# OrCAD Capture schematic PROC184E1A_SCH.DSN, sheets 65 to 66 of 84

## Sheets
65 74. POWER SUPPLY #3: size C; title: POWER SUPPLY #3; note: PROC184_SCH
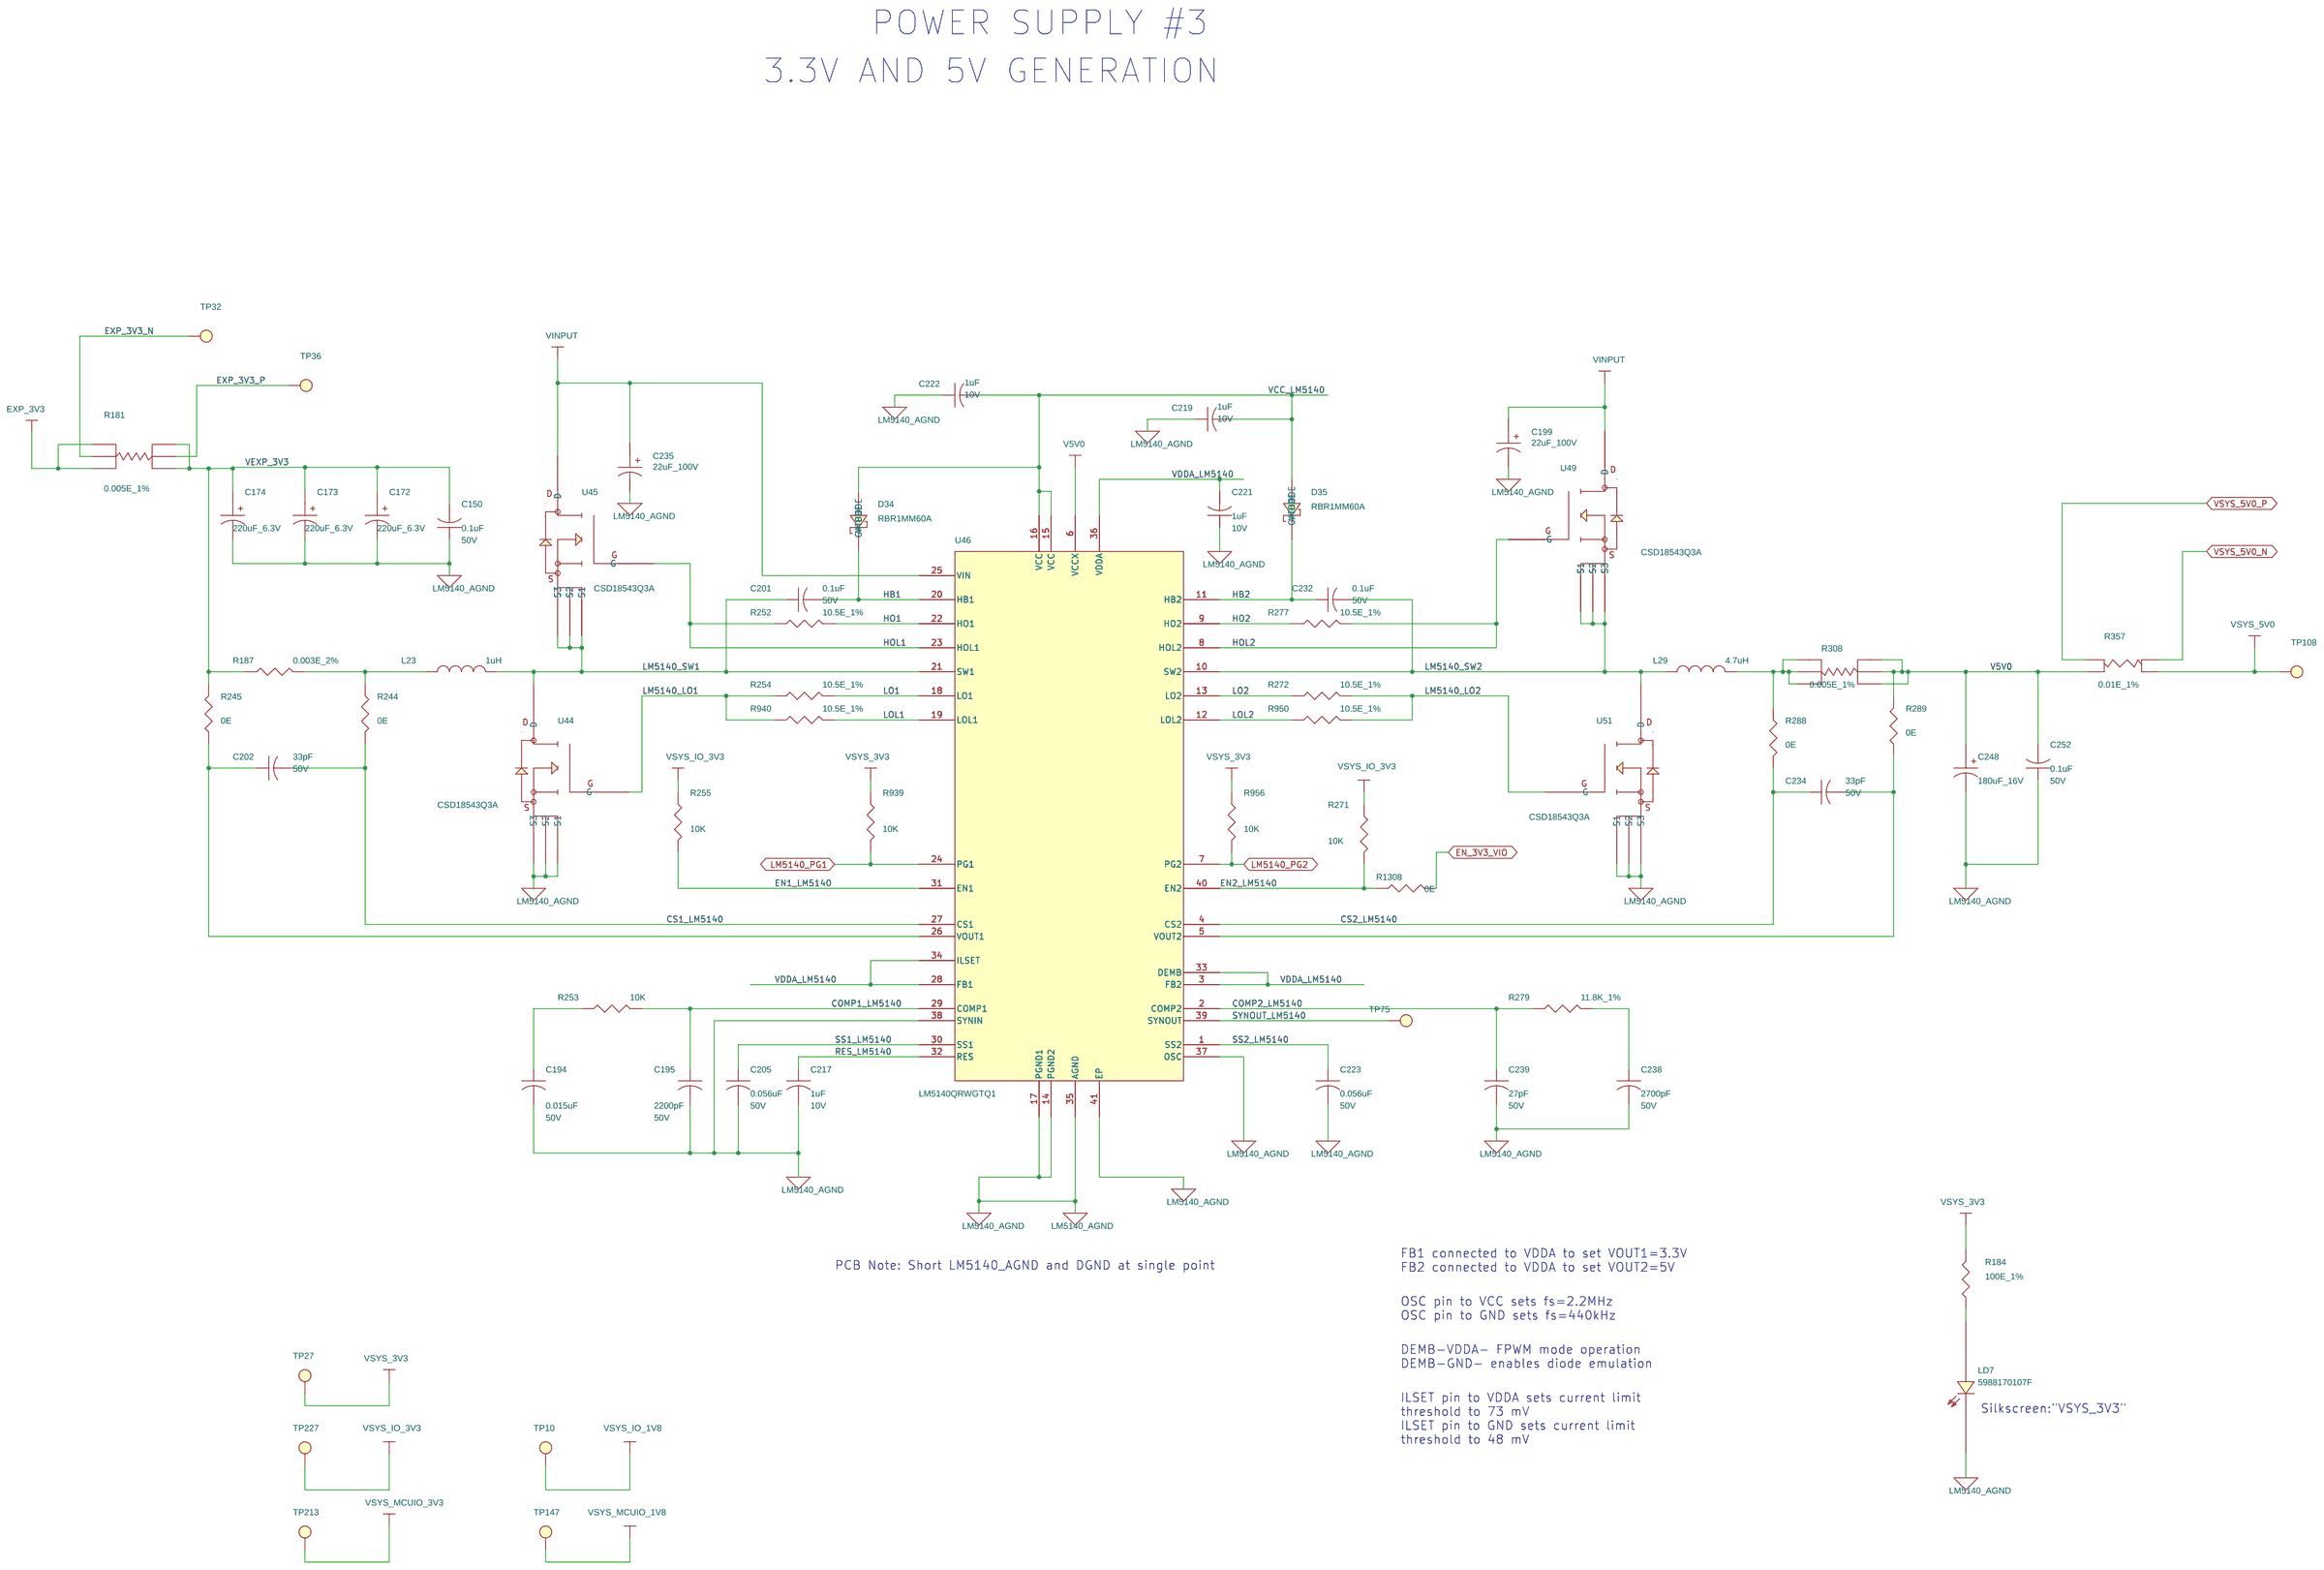
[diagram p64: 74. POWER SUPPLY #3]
66 73. POWER SUPPLY #2: size C; title: POWER SUPPLY #2; note: PROC184_SCH
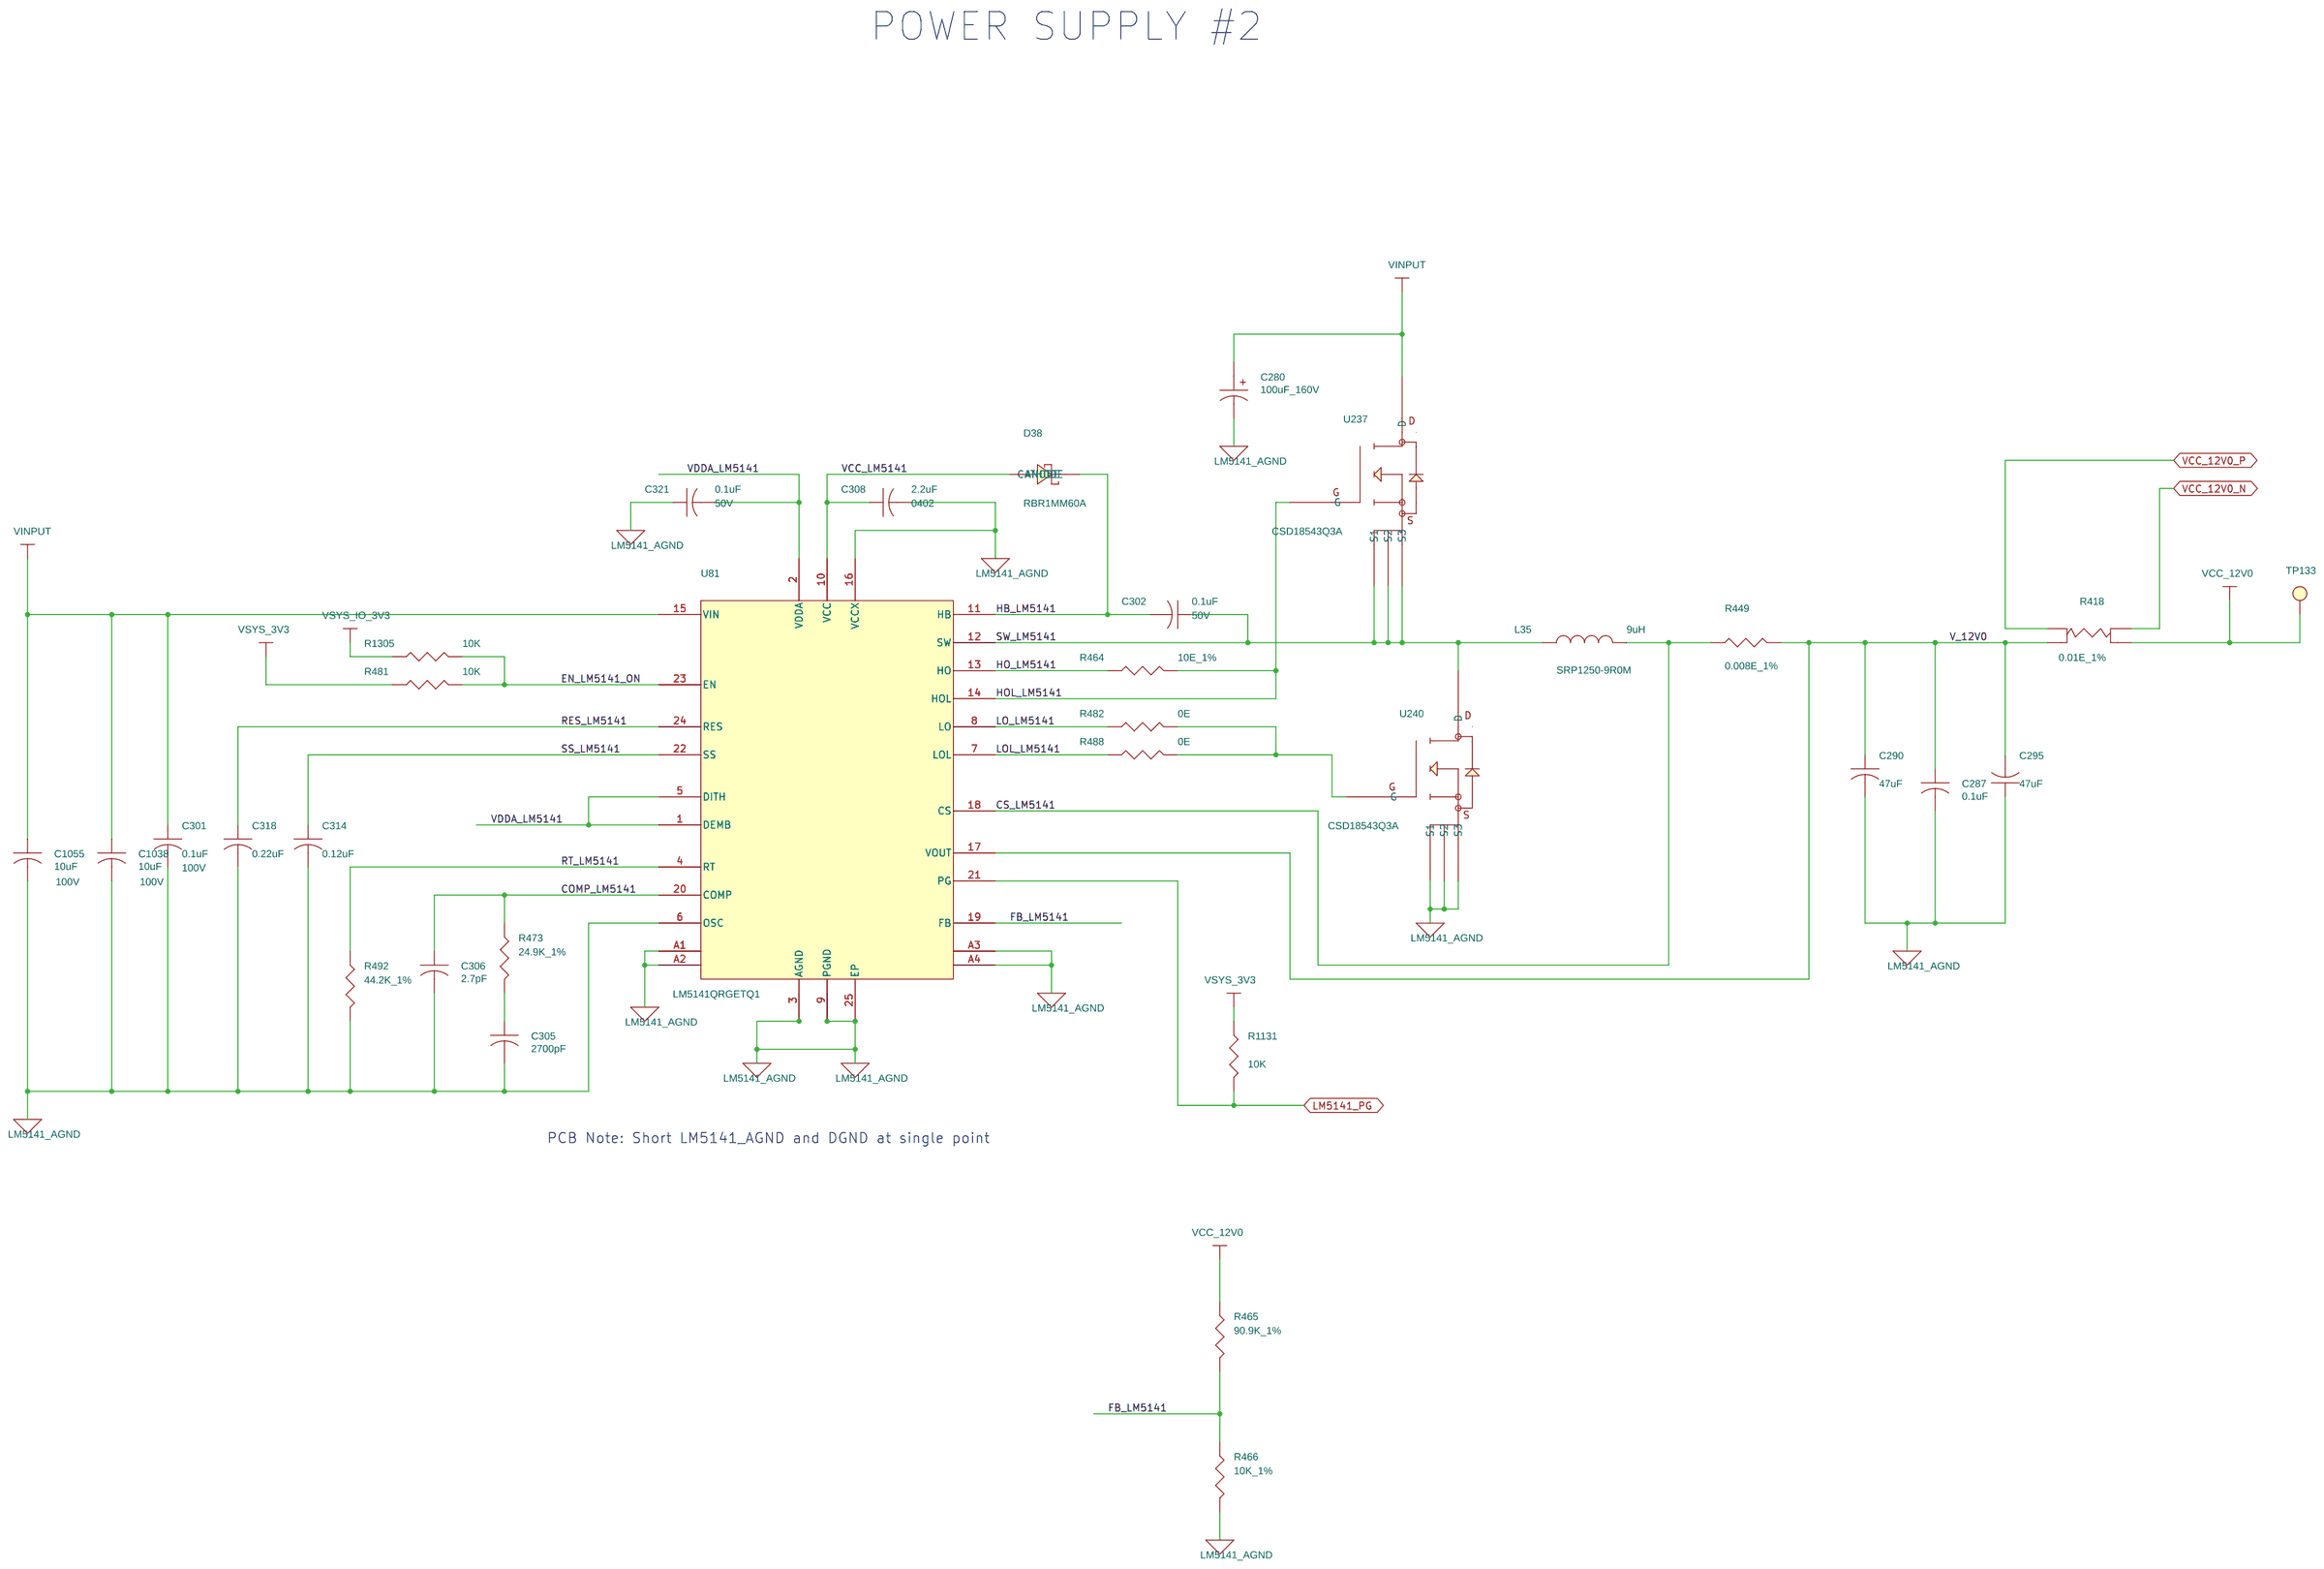
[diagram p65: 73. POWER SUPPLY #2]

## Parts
sheet 73. POWER SUPPLY #2
C280  100uF_160V  [CAPAE_CASE173173_22-5]
C287  0.1uF  [CAP0402_0-75]
C290  47uF  [CAP1206_2]
C295  47uF  [CAP1206_2]
C301  0.1uF  [CAP0603_1]
C302  0.1uF  [CAP0402_0-75]
C305  2700pF  [CAP0402_0-75]
C306  2.7pF  [CAP0402_0-75]
C308  2.2uF  [CAP0402_0-75]
C314  0.12uF  [CAP0603_1]
C318  0.22uF  [CAP0402_0-75]
C321  0.1uF  [CAP0402_0-75]
C1038  10uF  [CAP1210_2-75]
C1055  10uF  [CAP1210_2-75]
D38  RBR1MM60A  [DIO_SOD123F_0-9]
L35  9uH  [IND_SRP1250_550X530_SMD_5-2]
R418  0.01E_1%  [RES_KRL2012_0805-4_0-7_TI]
R449  0.008E_1%  [RES1206_0-75]
R464  10E_1%  [RES0402_0-5]
R465  90.9K_1%  [RES0402_0-5]
R466  10K_1%  [RES0402_0-5]
R473  24.9K_1%  [RES0402_0-5]
R481  10K  [RES0402_0-5]
R482  0E  [RES0402_0-5]
R488  0E  [RES0402_0-5]
R492  44.2K_1%  [RES0402_0-5]
R1131  10K  [RES0402_0-5]
R1305  10K  [RES0402_0-5]
TP133  THRU HOLE  [TP_40X65]
U81  LM5141QRGETQ1  [VQFN24_LM5141_160X160_1]
U237  CSD18543Q3A  [VSONP8_CSD18543Q_120X130_0-9]
U240  CSD18543Q3A  [VSONP8_CSD18543Q_120X130_0-9]
sheet 74. POWER SUPPLY #3
C150  0.1uF  [CAP0402_0-75]
C172  220uF_6.3V  [CAPAE_B6CASE_6]
C173  220uF_6.3V  [CAPAE_B6CASE_6]
C174  220uF_6.3V  [CAPAE_B6CASE_6]
C194  0.015uF  [CAP0805_1]
C195  2200pF  [CAP0805_1-5]
C199  22uF_100V  [CAPAE_CASE8383_10-5]
C201  0.1uF  [CAP0402_0-75]
C202  33pF  [CAP0402_0-75]
C205  0.056uF  [CAP1206_1-25]
C217  1uF  [CAP0402_0-75]
C219  1uF  [CAP0402_0-75]
C221  1uF  [CAP0402_0-75]
C222  1uF  [CAP0402_0-75]
C223  0.056uF  [CAP1206_1-25]
C232  0.1uF  [CAP0402_0-75]
C234  33pF  [CAP0402_0-75]
C235  22uF_100V  [CAPAE_CASE8383_10-5]
C238  2700pF  [CAP0805_1-5]
C239  27pF  [CAP0805_0-75]
C248  180uF_16V  [CAPAE_C6CASE_6]
C252  0.1uF  [CAP0402_0-75]
D34  RBR1MM60A  [DIO_SOD123F_0-9]
D35  RBR1MM60A  [DIO_SOD123F_0-9]
L23  1uH  [IND_HLP5050CE-1R0-01_530X510_SMD_3-5]
L29  4.7uH  [IND_XAL6060_260X270_SMD_6-1]
LD7  5988170107F  [LED_0805_0-7]
R181  0.005E_1%  [RES_KRL3216_1206-6_0-7_TI]
R184  100E_1%  [RES0402_0-5]
R187  0.003E_2%  [RES1206_W_0-75]
R244  0E  [RES0402_0-5]
R245  0E  [RES0402_0-5]
R252  10.5E_1%  [RES0402_0-5]
R253  10K  [RES0402_0-5]
R254  10.5E_1%  [RES0402_0-5]
R255  10K  [RES0402_0-5]
R271  10K  [RES0402_0-5]
R272  10.5E_1%  [RES0402_0-5]
R277  10.5E_1%  [RES0402_0-5]
R279  11.8K_1%  [RES0402_0-5]
R288  0E  [RES0402_0-5]
R289  0E  [RES0402_0-5]
R308  0.005E_1%  [RES_KRL3216_1206-6_0-7_TI]
R357  0.01E_1%  [RES_KRL2012_0805-4_0-7_TI]
R939  10K  [RES0402_0-5]
R940  10.5E_1%  [RES0402_0-5]
R950  10.5E_1%  [RES0402_0-5]
R956  10K  [RES0402_0-5]
R1308  0E  [RES0402_0-5]
TP10  THRU HOLE  [TP_40X65]
TP27  THRU HOLE  [TP_40X65]
TP32  THRU HOLE  [TP_40X65]
TP36  THRU HOLE  [TP_40X65]
TP75  TP40_SMD  [TP40_SMD]
TP108  THRU HOLE  [TP_40X65]
TP147  TP40_SMD  [TP40_SMD]
TP213  THRU HOLE  [TP_40X65]
TP227  THRU HOLE  [TP_40X65]
U44  CSD18543Q3A  [VSONP8_CSD18543Q_120X130_0-9]
U45  CSD18543Q3A  [VSONP8_CSD18543Q_120X130_0-9]
U46  LM5140QRWGTQ1  [QFN40_19-68_240X240_0-9_EP3-4]
U49  CSD18543Q3A  [VSONP8_CSD18543Q_120X130_0-9]
U51  CSD18543Q3A  [VSONP8_CSD18543Q_120X130_0-9]

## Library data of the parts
C280 = CAP_POL: CAP ELECTROLYTIC 100uF 160V 20% CASE_173173; Chkd/date: MANIRAJA/110222; Crtd /date: ALVY/100222; Custom_Duty: 15%; Customs_HS_Code: 85322990; Distributor_name: MOUSER; Distributor_part_number: 647-UUJ2C101MNQ1MS; Footprint Path: Y:\MIS_DATABASE\Library\ALTIUM_TOOL\PCB_FOOTPRINTS\Altium_Footprint_Lib.PcbLib; Height: 22.50MM; Library Path: Y:\MIS_DATABASE\Library\ALTIUM_TOOL\SCHEMATICS_PARTS\MS_DISCRETE_Library.schlib; Manufacturer: NICHICON; Mfr_name: NICHICON; Mfr_part_number: UUJ2C101MNQ1MS; Mistral Part No: 120022020007-R; Package: CASE_173173; Part_type: CAPACITORS\ELECTROLYTIC; Project: TI_J7AHP_EVM_BRD; RoHS: RoHS; Temperature: -40°C+105°C; Tolerance: 20%; Voltage: 160V; Wattage: NA; Weight: 6170mg; Datasheet: Y:\MIS_DATABASE\DATASHEETS\CAPACITORS\UUJ-SER.PDF
C287 = CAP: CAP CERAMIC 0.1uF 50V 10% X7R 0402; Chkd/date: MANIRAJA/261020; Crtd /date: ALVY/211020; Custom_Duty: 15%; Customs_HS_Code: 85322990; Distributor_name: DIGIKEY; Distributor_part_number: 490-10700-1-ND; Footprint Path: Y:\MIS_DATABASE\Library\ALTIUM_TOOL\PCB_FOOTPRINTS\Altium_Footprint_Lib.PcbLib; Height: 0.55MM; Library Path: Y:\MIS_DATABASE\Library\ALTIUM_TOOL\SCHEMATICS_PARTS\MS_DISCRETE_Library.schlib; Mfr_name: MURATA; Mfr_part_number: GRM155R71H104KE14D; Mistral Part No: 120011100014-R; Package: 0402; Part_type: CAPACITORS\CERAMIC; Project: J7_CP; RoHS: RoHS; Temperature: -55°C+125°C; Tolerance: 10%; Voltage: 50V; Wattage: NA; Weight: 3.1mg; Datasheet: Y:\MIS_DATABASE\DATASHEETS\CAPACITORS\GRM155R71H104KE14.PDF
C290 C295 = CAP: CAP CERAMIC 47uF 25V 20% X5R 1206; Chkd/date: VASANTHA/261214; Crtd /date: USMAN/160513; Custom_Duty: 15%; Customs_HS_Code: 85322990; Distributor_name: DIGIKEY; Distributor_part_number: 445-8047-1-ND; Footprint Path: Y:\MIS_DATABASE\Library\ALTIUM_TOOL\PCB_FOOTPRINTS\Altium_Footprint_Lib.PcbLib; Height: 1.80MM; Library Path: Y:\MIS_DATABASE\Library\ALTIUM_TOOL\SCHEMATICS_PARTS\MS_DISCRETE_Library.schlib; Manufacturer: TDK CORPORATION; Mfr_name: TDK CORPORATION; Mfr_part_number: C3216X5R1E476M160AC; Mistral Part No: 120013050002-R; Package: 1206; Part_type: CAPACITORS\CERAMIC; Project: ERP; RoHS: RoHS; Temperature: -55°C+85°C; Tolerance: 20%; Voltage: 25V; Wattage: NA; Weight: 16.2mg; Datasheet: Y:\MIS_DATABASE\DATASHEETS\CAPACITORS\TDK_C-SER-JUL17.PDF
C301 = CAP: CAP CERAMIC 0.1uF 100V 10% X7R 0603; Chkd/date: MANIRAJA/170420; Crtd /date: ALVY/170420; Custom_Duty: 15%; Customs_HS_Code: 85322990; Distributor_name: DIGIKEY; Distributor_part_number: 490-3285-1-ND; Footprint Path: Y:\MIS_DATABASE\Library\ALTIUM_TOOL\PCB_FOOTPRINTS\Altium_Footprint_Lib.PcbLib; Height: 0.90MM; Library Path: Y:\MIS_DATABASE\Library\ALTIUM_TOOL\SCHEMATICS_PARTS\MS_DISCRETE_Library.schlib; Manufacturer: MURATA; Mfr_name: MURATA; Mfr_part_number: GRM188R72A104KA35D; Mistral Part No: 120017010012-R; Package: 0603; Part_type: CAPACITORS\CERAMIC; Project: CUSTOM DCA1000; RoHS: RoHS; Temperature: -55°C+125°C; Tolerance: 10%; Voltage: 100V; Wattage: NA; Weight: 6.3mg; Datasheet: Y:\MIS_DATABASE\DATASHEETS\CAPACITORS\GRM188R72A104KA35.PDF
C302 C321 = CAP: CAP CERAMIC 0.1uF 50V 10% X7R 0402; Chkd/date: MANIRAJA/261020; Crtd /date: ALVY/211020; Custom_Duty: 15%; Customs_HS_Code: 85322990; Distributor_name: DIGIKEY; Distributor_part_number: 490-10700-1-ND; Footprint Path: Y:\MIS_DATABASE\Library\ALTIUM_TOOL\PCB_FOOTPRINTS\Altium_Footprint_Lib.PcbLib; Height: 0.55MM; Library Path: Y:\MIS_DATABASE\Library\ALTIUM_TOOL\SCHEMATICS_PARTS\MS_DISCRETE_Library.schlib; Manufacturer: MURATA; Mfr_name: MURATA; Mfr_part_number: GRM155R71H104KE14D; Mistral Part No: 120011100014-R; Package: 0402; Part_type: CAPACITORS\CERAMIC; Project: J7_CP; RoHS: RoHS; Temperature: -55°C+125°C; Tolerance: 10%; Voltage: 50V; Wattage: NA; Weight: 3.1mg; Datasheet: Y:\MIS_DATABASE\DATASHEETS\CAPACITORS\GRM155R71H104KE14.PDF
C305 = CAP: CAP CERAMIC 2700pF 50V 10% X7R 0402; Chkd/date: VASANTHA/201216; Crtd /date: CHAITHANYA/071111; Custom_Duty: 15%; Customs_HS_Code: 85322990; Distributor_name: DIGIKEY; Distributor_part_number: 490-1306-1-ND; Footprint Path: Y:\MIS_DATABASE\Library\ALTIUM_TOOL\PCB_FOOTPRINTS\Altium_Footprint_Lib.PcbLib; Height: 0.55MM; Library Path: Y:\MIS_DATABASE\Library\ALTIUM_TOOL\SCHEMATICS_PARTS\MS_DISCRETE_Library.schlib; Manufacturer: MURATA; Mfr_name: MURATA; Mfr_part_number: GRM155R71H272KA01D; Mistral Part No: 120011110004-R; Package: 0402; Part_type: CAPACITORS\CERAMIC; Project: DLRL_FPGA_DEV_PF; RoHS: RoHS; Temperature: -55°C+125°C; Tolerance: 10%; Voltage: 50V; Wattage: NA; Weight: 6mg; Datasheet: Y:\MIS_DATABASE\DATASHEETS\CAPACITORS\GRM155R71H272KA01.PDF
C306 = CAP: CAP CERAMIC 2.7pF 50V 0.25pF HI-Q C0G(NP0) 0402; Chkd/date: USMAN/200513; Crtd /date: USMAN/190313; Custom_Duty: 15%; Customs_HS_Code: 85322990; Distributor_name: DIGIKEY; Distributor_part_number: 490-3093-1-ND; Footprint Path: Y:\MIS_DATABASE\Library\ALTIUM_TOOL\PCB_FOOTPRINTS\Altium_Footprint_Lib.PcbLib; Height: 0.55MM; Library Path: Y:\MIS_DATABASE\Library\ALTIUM_TOOL\SCHEMATICS_PARTS\MS_DISCRETE_Library.schlib; Manufacturer: MURATA; Mfr_name: MURATA; Mfr_part_number: GJM1555C1H2R7CB01D; Mistral Part No: 120013030006-R; Package: 0402; Part_type: CAPACITORS\CERAMIC; Project: DTRM; RoHS: RoHS; Temperature: -55°C+125°C; Tolerance: 0.25pF%; Voltage: 50V; Wattage: NA; Weight: 6mg; Datasheet: Y:\MIS_DATABASE\DATASHEETS\CAPACITORS\MURATA-GXX-SER_NOV17.PDF
C308 = CAP: CAP CERAMIC 2.2uF 10V 10% X5R 0402; Chkd/date: MANIRAJA/251120; Crtd /date: ALVY/241120; Custom_Duty: 15%; Customs_HS_Code: 85322990; Distributor_name: MOUSER; Distributor_part_number: 81-GRM155R61A225K01D; Footprint Path: Y:\MIS_DATABASE\Library\ALTIUM_TOOL\PCB_FOOTPRINTS\Altium_Footprint_Lib.PcbLib; Height: 0.55MM; Library Path: Y:\MIS_DATABASE\Library\ALTIUM_TOOL\SCHEMATICS_PARTS\MS_DISCRETE_Library.schlib; Manufacturer: MURATA; Mfr_name: MURATA; Mfr_part_number: GRM155R61A225KE01D; Mistral Part No: 120011100038-R; Package: 0402; Part_type: CAPACITORS\CERAMIC; Project: PLCC_DIGITAL BRD PROTO; RoHS: RoHS; Temperature: -55°C+85°C; Tolerance: 10%; Voltage: 10V; Wattage: NA; Weight: 1.6mg; Datasheet: Y:\MIS_DATABASE\DATASHEETS\CAPACITORS\MURATA-GXX-SER_NOV17.PDF
C314 = CAP: CAP CERAMIC 0.12uF 10V 10% X7R 0603; Chkd/date: MANIRAJA/080519; Crtd /date: ALVY/080519; Custom_Duty: 15%; Customs_HS_Code: 85322990; Distributor_name: DIGIKEY; Distributor_part_number: 311-4056-1-ND; Footprint Path: Y:\MIS_DATABASE\Library\ALTIUM_TOOL\PCB_FOOTPRINTS\Altium_Footprint_Lib.PcbLib; Height: 0.90MM; Library Path: Y:\MIS_DATABASE\Library\ALTIUM_TOOL\SCHEMATICS_PARTS\MS_DISCRETE_Library.schlib; Manufacturer: YAGEO AMERICA; Mfr_name: YAGEO AMERICA; Mfr_part_number: CC0603KRX7R6BB124; Mistral Part No: 120019050003-R; Package: 0603; Part_type: CAPACITORS\CERAMIC; Project: BRUKER_SD820_COMMONDO; RoHS: RoHS; Temperature: -55°C+125°C; Tolerance: 10%; Voltage: 10V; Wattage: NA; Weight: 2mg; Datasheet: Y:\MIS_DATABASE\DATASHEETS\CAPACITORS\YACC-X7R.PDF
C318 = CAP: CAP CERAMIC 0.22uF 16V 10% X7R AUTO 0402; Chkd/date: MANIRAJA/031219; Crtd /date: ALVY/021219; Custom_Duty: 15%; Customs_HS_Code: 85322990; Distributor_name: DIGIKEY; Distributor_part_number: 490-10671-1-ND; Footprint Path: Y:\MIS_DATABASE\Library\ALTIUM_TOOL\PCB_FOOTPRINTS\Altium_Footprint_Lib.PcbLib; Height: 0.55MM; Library Path: Y:\MIS_DATABASE\Library\ALTIUM_TOOL\SCHEMATICS_PARTS\MS_DISCRETE_Library.schlib; Manufacturer: MURATA; Mfr_name: MURATA; Mfr_part_number: GCM155R71C224KE02D; Mistral Part No: 120019020006-R; Package: 0402; Part_type: CAPACITORS\CERAMIC; Project: GRACO_PLC_EXPN BOARD; RoHS: RoHS; Temperature: -55°C+125°C; Tolerance: 10%; Voltage: 16V; Wattage: NA; Weight: 12mg; Datasheet: Y:\MIS_DATABASE\DATASHEETS\CAPACITORS\MURATA-GCM-SER.PDF
C1038 C1055 = CAP: CAP CERAMIC 10uF 100V 10% X7S 1210; Chkd/date: MANIRAJA/280819; Crtd /date: MANIRAJA/280819; Custom_Duty: 15%; Customs_HS_Code: 85322990; Distributor_name: DIGIKEY; Distributor_part_number: 490-16266-1-ND; Footprint Path: Y:\MIS_DATABASE\Library\ALTIUM_TOOL\PCB_FOOTPRINTS\Altium_Footprint_Lib.PcbLib; Height: 2.70MM; Library Path: Y:\MIS_DATABASE\Library\ALTIUM_TOOL\SCHEMATICS_PARTS\MS_DISCRETE_Library.schlib; Manufacturer: MURATA; Mfr_name: MURATA; Mfr_part_number: GRM32EC72A106KE05L; Mistral Part No: 120019080009-R; Package: 1210; Part_type: CAPACITORS\CERAMIC; Project: TI_J7ES_GESI_EXP_BOARD; RoHS: RoHS; Temperature: -55°C+125°C; Tolerance: 10%; Voltage: 100V; Wattage: NA; Weight: 110mg; Datasheet: Y:\MIS_DATABASE\DATASHEETS\CAPACITORS\GRM32EC72A106KE05.PDF
D38 = DIODE_SCHOTTKY: DIODE SCHOTTKY RECTIFIER 60V 1A SOD-123FL; Chkd/date: ALVY/240322; Crtd /date: TAMILARASU/220322; Custom_Duty: 15%; Customs_HS_Code: 85412900; Distributor_name: DIGIKEY; Distributor_part_number: RBR1MM60ACT-ND; Footprint Path: Y:\MIS_DATABASE\Library\ALTIUM_TOOL\PCB_FOOTPRINTS\Altium_Footprint_Lib.PcbLib; Height: 0.90MM; Library Path: Y:\MIS_DATABASE\Library\ALTIUM_TOOL\SCHEMATICS_PARTS\MS_DISCRETE_Library.schlib; Manufacturer: TOREX; Mfr_name: ROHM; Mfr_part_number: RBR1MM60ATR; Mistral Part No: 130022030051-R; Package: SOD-123FL; Part_type: DIODE\SCHOTTKY; Project: TI_J7AHP_EVM_BRD; RoHS: RoHS; Temperature: NA; Tolerance: NA; Voltage: 60V; Wattage: NA; Weight: 27.827mg; Datasheet: Y:\MIS_DATABASE\DATASHEETS\DISCRETES\DIODES\RBR1MM60A.PDF
L35 = INDUCTOR: IND POWER 9uH 10A 20% SMD; Chkd/date: ALVY/150222; Crtd /date: TAMILARASU/150222; Custom_Duty: 24%; Customs_HS_Code: 85437099; Distributor_name: DIGIKEY; Distributor_part_number: SRP1250-9R0MCT-ND; Footprint Path: Y:\MIS_DATABASE\Library\ALTIUM_TOOL\PCB_FOOTPRINTS\Altium_Footprint_Lib.PcbLib; Height: 5.20MM; Library Path: Y:\MIS_DATABASE\Library\ALTIUM_TOOL\SCHEMATICS_PARTS\MS_DISCRETE_Library.schlib; Manufacturer: BOURNS; Mfr_name: BOURNS; Mfr_part_number: SRP1250-9R0M; Mistral Part No: 130022020033-R; Package: SMD; Project: TI_J7AHP_EVM_BRD; RoHS: RoHS; Temperature: -55°C+150°C; Tolerance: 20%; Voltage: NA; Wattage: NA; Weight: 5834mg; Datasheet: Y:\MIS_DATABASE\DATASHEETS\DISCRETES\INDUCTORS\SRP1250-SER-JUN19.PDF
R357 R418 = RESISTOR-4TERM: RES 0.01E 1W 1% 0805-W; Chkd/date: MANIRAJA/301118; Crtd /date: MANIRAJA/301118; Custom_Duty: 15%; Customs_HS_Code: 85332119; Distributor_name: MOUSER; Distributor_part_number: 754-KRL2012ECR010FT5; Footprint Path: Y:\MIS_DATABASE\Library\ALTIUM_TOOL\PCB_FOOTPRINTS\Altium_Footprint_Lib.PcbLib; Height: 0.70MM; Library Path: Y:\MIS_DATABASE\Library\ALTIUM_TOOL\SCHEMATICS_PARTS\MS_DISCRETE_Library.schlib; Manufacturer: SUSUMU; Mfr_name: SUSUMU; Mfr_part_number: KRL2012E-C-R010-F-T5_TI4; Mistral Part No: 110018110013-R; Package: 0805-W; Part_type: RESISTORS\FIXED; Project: TI_J7ES_EVM_SOM; RoHS: RoHS; Temperature: -55°C+175°C; Tolerance: 1%; Voltage: NA; Wattage: 1W; Weight: NA; Datasheet: Y:\MIS_DATABASE\DATASHEETS\RESISTORS\KRL_TI-SERIES.PDF
R449 = RESISTOR: RES 0.008E 1W 1% AUTO 1206; Chkd/date: ALVY/040122; Crtd /date: MANIRAJA/040122; Custom_Duty: 15%; Customs_HS_Code: 85332119; Distributor_name: DIGIKEY; Distributor_part_number: RHM.008ALCT-ND; Footprint Path: Y:\MIS_DATABASE\Library\ALTIUM_TOOL\PCB_FOOTPRINTS\Altium_Footprint_Lib.PcbLib; Height: 0.59MM; Library Path: Y:\MIS_DATABASE\Library\ALTIUM_TOOL\SCHEMATICS_PARTS\MS_DISCRETE_Library.schlib; Manufacturer: ROHM; Mfr_name: ROHM; Mfr_part_number: PMR18EZPFU8L00; Mistral Part No: 110022010001-R; Package: 1206; Part_type: RESISTORS\FIXED; Project: BRUKER_SD820_COMMONDO; RoHS: RoHS; Temperature: -55°C+155°C; Tolerance: 1%; Voltage: NA; Wattage: 1W; Weight: 16.2mg; Datasheet: Y:\MIS_DATABASE\DATASHEETS\RESISTORS\PMR-SER_REVJ.PDF
R464 = RESISTOR: RES 10E 1/10W 1% 0402; Chkd/date: VASANTHA/201216; Crtd /date: MAZHAR/120505; Custom_Duty: 15%; Customs_HS_Code: 85332119; Distributor_name: DIGIKEY; Distributor_part_number: P10.0LCT-ND; Footprint Path: Y:\MIS_DATABASE\Library\ALTIUM_TOOL\PCB_FOOTPRINTS\Altium_Footprint_Lib.PcbLib; Height: 0.40MM; Library Path: Y:\MIS_DATABASE\Library\ALTIUM_TOOL\SCHEMATICS_PARTS\MS_DISCRETE_Library.schlib; Manufacturer: PANASONIC-ECG; Mfr_name: PANASONIC-ECG; Mfr_part_number: ERJ-2RKF10R0X; Mistral Part No: 110009030203-R; Package: 0402; Part_type: RESISTORS\FIXED; Project: CTP02_REVA_BASE; RoHS: RoHS; Temperature: -55°C+155°C; Tolerance: 1%; Voltage: NA; Wattage: 1/10W; Weight: 0.8mg; Datasheet: Y:\MIS_DATABASE\DATASHEETS\RESISTORS\PAN-ERJSER_NOV17.PDF
R465 = RESISTOR: RES 90.9K 1/10W 1% 0402; Chkd/date: ALVY/210222; Crtd /date: TAMILARASU/210222; Custom_Duty: 15%; Customs_HS_Code: 85332119; Distributor_name: DIGIKEY; Distributor_part_number: 2019-RK73G1ETTP9092FCT-ND; Footprint Path: Y:\MIS_DATABASE\Library\ALTIUM_TOOL\PCB_FOOTPRINTS\Altium_Footprint_Lib.PcbLib; Height: 0.40MM; Library Path: Y:\MIS_DATABASE\Library\ALTIUM_TOOL\SCHEMATICS_PARTS\MS_DISCRETE_Library.schlib; Manufacturer: KOA SPEER; Mfr_name: KOA SPEER; Mfr_part_number: RK73G1ETTP9092F; Mistral Part No: 110022020011-R; Package: 0402; Part_type: RESISTORS\FIXED; Project: TI_J7AHP_EVM_BRD; RoHS: RoHS; Temperature: -55°C+155°C; Tolerance: 1%; Voltage: NA; Wattage: 1/10W; Weight: 0.65mg; Datasheet: Y:\MIS_DATABASE\DATASHEETS\RESISTORS\RK73G-SER.PDF
R466 = RESISTOR: RES 10K 1/16W 1% 0402; Chkd/date: VASANTHA/201216; Crtd /date: GEETHA/290506; Custom_Duty: 15%; Customs_HS_Code: 85332119; Distributor_name: DIGIKEY; Distributor_part_number: 311-10.0KLRTR-ND; Footprint Path: Y:\MIS_DATABASE\Library\ALTIUM_TOOL\PCB_FOOTPRINTS\Altium_Footprint_Lib.PcbLib; Height: 0.40MM; Library Path: Y:\MIS_DATABASE\Library\ALTIUM_TOOL\SCHEMATICS_PARTS\MS_DISCRETE_Library.schlib; Manufacturer: YAGEO AMERICA; Mfr_name: YAGEO AMERICA; Mfr_part_number: RC0402FR-0710KL; Mistral Part No: 110015090015-R; Package: 0402; Part_type: RESISTORS\FIXED; Project: VOCERA; RoHS: RoHS; Temperature: -55°C+155°C; Tolerance: 1%; Voltage: NA; Wattage: 1/16W; Weight: 0.65mg; Datasheet: Y:\MIS_DATABASE\DATASHEETS\RESISTORS\RCXXXXL-SER_MAR18.PDF
R473 = RESISTOR: RES 24.9K 1/16W 1% 0402; Chkd/date: MANIRAJA/121017; Crtd /date: MANIRAJA/121017; Custom_Duty: 15%; Customs_HS_Code: 85332119; Distributor_name: DIGIKEY; Distributor_part_number: 311-24.9KLRCT-ND; Footprint Path: Y:\MIS_DATABASE\Library\ALTIUM_TOOL\PCB_FOOTPRINTS\Altium_Footprint_Lib.PcbLib; Height: 0.40MM; Library Path: Y:\MIS_DATABASE\Library\ALTIUM_TOOL\SCHEMATICS_PARTS\MS_DISCRETE_Library.schlib; Manufacturer: YAGEO AMERICA; Mfr_name: YAGEO AMERICA; Mfr_part_number: RC0402FR-0724K9L; Mistral Part No: 110009030538-R; Package: 0402; Part_type: RESISTORS\FIXED; Project: P4_RADAR_DI; RoHS: RoHS; Temperature: -55°C+155°C; Tolerance: 1%; Voltage: NA; Wattage: 1/16W; Weight: 0.65mg; Datasheet: Y:\MIS_DATABASE\DATASHEETS\RESISTORS\RCXXXXL-SER_MAR18.PDF
R253 R255 R271 R481 R939 R956 R1131 R1305 = RESISTOR: RES 10K 1/16W 5% 0402; Chkd/date: VASANTHA/061216; Crtd /date: MAZHAR/230805; Custom_Duty: 15%; Customs_HS_Code: 85332119; Distributor_name: DIGIKEY; Distributor_part_number: 311-10KJRCT-ND; Footprint Path: Y:\MIS_DATABASE\Library\ALTIUM_TOOL\PCB_FOOTPRINTS\Altium_Footprint_Lib.PcbLib; Height: 0.40MM; Library Path: Y:\MIS_DATABASE\Library\ALTIUM_TOOL\SCHEMATICS_PARTS\MS_DISCRETE_Library.schlib; Manufacturer: YAGEO AMERICA; Mfr_name: YAGEO AMERICA; Mfr_part_number: RC0402JR-0710KL; Mistral Part No: 110011060021-R; Package: 0402; Part_type: RESISTORS\FIXED; Project: HSE; RoHS: RoHS; Temperature: -55°C+155°C; Tolerance: 5%; Voltage: NA; Wattage: 1/16W; Weight: 0.65mg; Datasheet: Y:\MIS_DATABASE\DATASHEETS\RESISTORS\RCXXXXL-SER_MAR18.PDF
R244 R245 R288 R289 R482 R488 R1308 = RESISTOR: RES 0E 1/10W JUMPER 0402; Chkd/date: VASANTHA/061216; Crtd /date: NAVEED/201014; Custom_Duty: 15%; Customs_HS_Code: 85332119; Distributor_name: DIGIKEY; Distributor_part_number: P0.0JCT-ND; Footprint Path: Y:\MIS_DATABASE\Library\ALTIUM_TOOL\PCB_FOOTPRINTS\Altium_Footprint_Lib.PcbLib; Height: 0.40MM; IBISSP_MODLES: VALUE REPEATING 2 TIME; Library Path: Y:\MIS_DATABASE\Library\ALTIUM_TOOL\SCHEMATICS_PARTS\MS_DISCRETE_Library.schlib; Manufacturer: PANASONIC-ECG; Mfr_name: PANASONIC-ECG; Mfr_part_number: ERJ-2GE0R00X; Mistral Part No: 110018030052-R; Package: 0402; Part_type: RESISTORS\FIXED; Project: AEGIS POM; RoHS: RoHS; Temperature: -55°C+155°C; Tolerance: NA; Voltage: NA; Wattage: 1/10W; Weight: 0.8mg; Datasheet: Y:\MIS_DATABASE\DATASHEETS\RESISTORS\PAN-ERJSER_NOV17.PDF
R492 = RESISTOR: RES 44.2K 1/16W 1% 0402; Chkd/date: ALVY/041120; Crtd /date: ALVY/041120; Custom_Duty: 15%; Customs_HS_Code: 85332119; Distributor_name: DIGIKEY; Distributor_part_number: 541-4106-1-ND; Footprint Path: Y:\MIS_DATABASE\Library\ALTIUM_TOOL\PCB_FOOTPRINTS\Altium_Footprint_Lib.PcbLib; Height: 0.35MM; Library Path: Y:\MIS_DATABASE\Library\ALTIUM_TOOL\SCHEMATICS_PARTS\MS_DISCRETE_Library.schlib; Manufacturer: VISHAY; Mfr_name: VISHAY; Mfr_part_number: CRCW040244K2FKEDC; Mistral Part No: 110010070032-R; Package: 0402; Part_type: RESISTORS\FIXED; Project: TI_J7ES_EVM_FUSION2_SER_CAP; RoHS: RoHS; Temperature: -55°C+155°C; Tolerance: 1%; Voltage: NA; Wattage: 1/16W; Weight: 0.65mg; Datasheet: Y:\MIS_DATABASE\DATASHEETS\RESISTORS\CRCW_C-SER.PDF
TP10 TP27 TP32 TP36 TP108 TP133 TP213 TP227 = TESTPOINT: TESTPOINT 1.0MM DRILL PTH; Chkd/date: MAZHAR/271211; Crtd /date: SHREESHAIL/041005; Distributor_name: NA; Distributor_part_number: NA; Height: NA; Manufacturer: LOCAL; Mfr_name: LOCAL; Mistral Part No: 130009030938; Package: THRU-HOLE; Project: HSE; Datasheet: NA
U81 = LM5141RGET_VQFN24: IC WIDE I/P RANGE SYNCHRONOUS BUCK CONTROLLER VQFN24; Automotive Alternate_mfr_name: TEXAS INSTRUMENTS; Chkd/date: MANIRAJA/031018; Crtd /date: MANIRAJA/031018; Custom_Duty: 15%; Customs_HS_Code: 85423100; Distributor_name: DIGIKEY; Distributor_part_number: 296-44870-1-ND; Footprint Path: Y:\MIS_DATABASE\Library\ALTIUM_TOOL\PCB_FOOTPRINTS\Altium_Footprint_Lib.PcbLib; Height: 1.00MM; Library Path: Y:\MIS_DATABASE\Library\ALTIUM_TOOL\SCHEMATICS_PARTS\MS_MISCPOWER_Library.schlib; Manufacturer: TEXAS INSTRUMENTS; Mfr_name: TEXAS INSTRUMENTS; Mistral Part No: 142018100002-R; Package: VQFN24; Part_type: ICS\POWER\CONTROL; Project: TI_J7ES_EVM_CP; RoHS: RoHS; Temperature: -40°C+150°C; Tolerance: NA; Voltage: NA; Wattage: NA; Weight: NA; Datasheet: Y:\MIS_DATABASE\DATASHEETS\ICS\POWER\LM5141-Q1.PDF
U44 U45 U49 U51 U237 U240 = MOSFET_CSD18501Q5A_TI: IC MOSFET N-CHANNEL 60V VSONP8; Chkd/date: MANIRAJA/041017; Crtd /date: MANIRAJA/041017; Custom_Duty: 15%; Customs_HS_Code: 85423100; Distributor_name: DIGIKEY; Distributor_part_number: 296-47321-1-ND; Footprint Path: Y:\MIS_DATABASE\Library\ALTIUM_TOOL\PCB_FOOTPRINTS\Altium_Footprint_Lib.PcbLib; Height: 0.90MM; Library Path: Y:\MIS_DATABASE\Library\ALTIUM_TOOL\SCHEMATICS_PARTS\MS_MOSFET_Library.schlib; Library Ref: MOSFET_CSD18501Q5A; Manufacturer: TEXAS INSTRUMENTS; Mfr_name: TEXAS INSTRUMENTS; Mistral Part No: 142017100004-R; Package: VSONP8; Part_type: ICS\POWER\MOSFET; Project: TI_MAXIE_CPB; RoHS: RoHS; Temperature: -55°C+150°C; Tolerance: NA; Voltage: 60V; Wattage: NA; Weight: NA; Datasheet: Y:\MIS_DATABASE\DATASHEETS\ICS\POWER\CSD18543Q3A.PDF
C150 C201 C232 C252 = CAP: CAP CERAMIC 0.1uF 50V 10% X7R 0402; Automotive Alternate_mfr_name: TDK; Automotive Alternate_mfr_part_number: CGA2B3X7R1H104K050BB; Chkd/date: MANIRAJA/261020; Crtd /date: ALVY/211020; Custom_Duty: 15%; Customs_HS_Code: 85322990; Direct Alternate_mfr_name: TDK; Direct Alternate_mfr_part_number: C1005X7R1H104K050BE; Distributor_name: DIGIKEY; Distributor_part_number: 490-10700-1-ND; Footprint Path: Y:\MIS_DATABASE\Library\ALTIUM_TOOL\PCB_FOOTPRINTS\Altium_Footprint_Lib.PcbLib; Height: 0.55MM; Library Path: Y:\MIS_DATABASE\Library\ALTIUM_TOOL\SCHEMATICS_PARTS\MS_DISCRETE_Library.schlib; Manufacturer: MURATA; Mfr_name: MURATA; Mfr_part_number: GRM155R71H104KE14D; Mistral Part No: 120011100014-R; Package: 0402; Part_type: CAPACITORS\CERAMIC; Project: J7_CP; RoHS: RoHS; Temperature: -55°C+125°C; Tolerance: 10%; Voltage: 50V; Wattage: NA; Weight: 3.1mg; Datasheet: Y:\MIS_DATABASE\DATASHEETS\CAPACITORS\GRM155R71H104KE14.PDF
C172-C174 = CAP_POL: CAP POLYMER 220uF 6.3V 20% B6CASE_5353; Chkd/date: MANIRAJA/110918; Crtd /date: ALVY/110918; Custom_Duty: 15%; Customs_HS_Code: 85322990; Distributor_name: DIGIKEY; Distributor_part_number: P16836CT-ND; Footprint Path: Y:\MIS_DATABASE\Library\ALTIUM_TOOL\PCB_FOOTPRINTS\Altium_Footprint_Lib.PcbLib; Height: 6.00MM; Library Path: Y:\MIS_DATABASE\Library\ALTIUM_TOOL\SCHEMATICS_PARTS\MS_DISCRETE_Library.schlib; Manufacturer: PANASONIC-ECG; Mfr_name: PANASONIC-ECG; Mfr_part_number: 6SVPE220MW; Mistral Part No: 120018090028-R; Package: B6CASE_5353; Part_type: CAPACITORS\POLYPROPYLENE; Project: TI_J7ES_EVM_CP; RoHS: RoHS; Temperature: -55°C+105°C; Tolerance: 20%; Voltage: 6.3V; Wattage: NA; Weight: NA; Datasheet: Y:\MIS_DATABASE\DATASHEETS\CAPACITORS\SVPE-SER.PDF
C194 = CAP: CAP CERAMIC 0.015uF 50V 5% C0G(NP0) 0805; Chkd/date: MANIRAJA/110918; Crtd /date: ALVY/110918; Custom_Duty: 15%; Customs_HS_Code: 85322990; Distributor_name: DIGIKEY; Distributor_part_number: 445-7521-1-ND; Footprint Path: Y:\MIS_DATABASE\Library\ALTIUM_TOOL\PCB_FOOTPRINTS\Altium_Footprint_Lib.PcbLib; Height: 1.00MM; Library Path: Y:\MIS_DATABASE\Library\ALTIUM_TOOL\SCHEMATICS_PARTS\MS_DISCRETE_Library.schlib; Manufacturer: TDK CORPORATION; Mfr_name: TDK CORPORATION; Mfr_part_number: C2012C0G1H153J085AA; Mistral Part No: 120018090031-R; Package: 0805; Part_type: CAPACITORS\CERAMIC; Project: TI_J7ES_EVM_CP; RoHS: RoHS; Temperature: -55°C+125°C; Tolerance: 5%; Voltage: 50V; Wattage: NA; Weight: 5.5mg; Datasheet: Y:\MIS_DATABASE\DATASHEETS\CAPACITORS\C2012C0G1H153J085AA.PDF
C195 = CAP: CAP CERAMIC 2200pF 50V 1% C0G(NP0) 0805; Chkd/date: MANIRAJA/070619; Crtd /date: MANIRAJA/070619; Custom_Duty: 15%; Customs_HS_Code: 85322990; Distributor_name: DIGIKEY; Distributor_part_number: 311-4157-1-ND; Footprint Path: Y:\MIS_DATABASE\Library\ALTIUM_TOOL\PCB_FOOTPRINTS\Altium_Footprint_Lib.PcbLib; Height: 1.45MM; Library Path: Y:\MIS_DATABASE\Library\ALTIUM_TOOL\SCHEMATICS_PARTS\MS_DISCRETE_Library.schlib; Manufacturer: YAGEO AMERICA; Mfr_name: YAGEO AMERICA; Mfr_part_number: CC0805FKNPO9BN222; Mistral Part No: 120011120002-R; Package: 0805; Part_type: CAPACITORS\CERAMIC; Project: J7ES_SOM_DUAL-LEO_PMIC; RoHS: RoHS; Temperature: -55°C+125°C; Tolerance: 1%; Voltage: 50V; Wattage: NA; Weight: 5.5mg; Datasheet: Y:\MIS_DATABASE\DATASHEETS\CAPACITORS\YACC-NPO.PDF
C199 C235 = CAP_POL: CAP ELECTROLYTIC 22uF 100V 20% CASE_8383; Chkd/date: ALVY/160222; Crtd /date: TAMILARASU/160222; Custom_Duty: 15%; Customs_HS_Code: 85322990; Distributor_name: DIGIKEY; Distributor_part_number: 493-6199-1-ND; Footprint Path: Y:\MIS_DATABASE\Library\ALTIUM_TOOL\PCB_FOOTPRINTS\Altium_Footprint_Lib.PcbLib; Height: 10.50MM; Library Path: Y:\MIS_DATABASE\Library\ALTIUM_TOOL\SCHEMATICS_PARTS\MS_DISCRETE_Library.schlib; Manufacturer: NICHICON; Mfr_name: NICHICON; Mfr_part_number: UUX2A220MNL6GS; Mistral Part No: 120022020014-R; Package: CASE_8383; Part_type: CAPACITORS\ELECTROLYTIC; Project: TI_J7AHP_EVM_BRD; RoHS: RoHS; Temperature: -55°C+105°C; Tolerance: 20%; Voltage: 100V; Wattage: NA; Weight: 800mg; Datasheet: Y:\MIS_DATABASE\DATASHEETS\CAPACITORS\UUX-SERIES.PDF
C202 C234 = CAP: CAP CERAMIC 33pF 50V 5% C0G(NP0) 0402; Assembly_Instruction: DNI; Chkd/date: NAVEED/260814; Crtd /date: BAVISH/080611; Custom_Duty: 15%; Customs_HS_Code: 85322990; Distributor_name: DIGIKEY; Distributor_part_number: 490-3220-1-ND; Footprint Path: Y:\MIS_DATABASE\Library\ALTIUM_TOOL\PCB_FOOTPRINTS\Altium_Footprint_Lib.PcbLib; Height: 0.55MM; Library Path: Y:\MIS_DATABASE\Library\ALTIUM_TOOL\SCHEMATICS_PARTS\MS_DISCRETE_Library.schlib; Manufacturer: MURATA; Mfr_name: MURATA; Mfr_part_number: GRM1555C1H330JZ01D; Mistral Part No: 120009030395-R; Package: 0402; Part_type: CAPACITORS\CERAMIC; Project: ACRO_DM3730; RoHS: RoHS; Temperature: -55°C+125°C; Tolerance: 5%; Voltage: 50V; Wattage: NA; Weight: 6mg; Datasheet: Y:\MIS_DATABASE\DATASHEETS\CAPACITORS\MURATA-GXX-SER_NOV17.PDF
C205 C223 = CAP: CAP CERAMIC 0.056uF 50V 5% C0G(NP0) 1206; Automotive Alternate_mfr_name: KEMET; Automotive Alternate_mfr_part_number: C1206X563K5RACAUTO; Chkd/date: MANIRAJA/110918; Crtd /date: ALVY/110918; Custom_Duty: 15%; Customs_HS_Code: 85322990; Direct Alternate_mfr_name: KEMET; Direct Alternate_mfr_part_number: C1206C563J5GAC7800; Distributor_name: DIGIKEY; Distributor_part_number: 490-8347-1-ND; Footprint Path: Y:\MIS_DATABASE\Library\ALTIUM_TOOL\PCB_FOOTPRINTS\Altium_Footprint_Lib.PcbLib; Height: 1.25MM; Library Path: Y:\MIS_DATABASE\Library\ALTIUM_TOOL\SCHEMATICS_PARTS\MS_DISCRETE_Library.schlib; Manufacturer: MURATA; Mfr_name: MURATA; Mfr_part_number: GRM31M5C1H563JA01L; Mistral Part No: 120018090032-R; Package: 1206; Part_type: CAPACITORS\CERAMIC; Project: TI_J7ES_EVM_CP; RoHS: RoHS; Temperature: -55°C+125°C; Tolerance: 5%; Voltage: 50V; Wattage: NA; Weight: 40mg; Datasheet: Y:\MIS_DATABASE\DATASHEETS\CAPACITORS\GRM31M5C1H563JA01L.PDF
C217 C219 C221 C222 = CAP: CAP CERAMIC 1uF 10V 10% X7S AUTO 0402; Automotive Alternate_mfr_name: TAIYO YUDEN; Automotive Alternate_mfr_part_number: EMK105BJ105KVHF; Chkd/date: MANIRAJA/100918; Crtd /date: ALVY/100918; Custom_Duty: 15%; Customs_HS_Code: 85322990; Direct Alternate_mfr_name: YAGEO AMERICA; Direct Alternate_mfr_part_number: CC0402KRX5R7BB105; Distributor_name: DIGIKEY; Distributor_part_number: 490-13409-1-ND; Footprint Path: Y:\MIS_DATABASE\Library\ALTIUM_TOOL\PCB_FOOTPRINTS\Altium_Footprint_Lib.PcbLib; Height: 0.70MM; Library Path: Y:\MIS_DATABASE\Library\ALTIUM_TOOL\SCHEMATICS_PARTS\MS_DISCRETE_Library.schlib; Manufacturer: TDK CORPORATION; Mfr_name: MURATA; Mfr_part_number: GCM155C71A105KE38D; Mistral Part No: 120018090021-R; Package: 0402; Part_type: CAPACITORS\CERAMIC; Project: SMART-M_SCRIPTALK_PB; RoHS: RoHS; Temperature: -55°C+125°C; Tolerance: 10%; Voltage: 10V; Wattage: NA; Weight: 6mg; Datasheet: Y:\MIS_DATABASE\DATASHEETS\CAPACITORS\MURATA-GCM-SER.PDF
C238 = CAP: CAP CERAMIC 2700pF 50V 2% C0G(NP0) 0805; Chkd/date: MANIRAJA/280920; Crtd /date: ALVY/250920; Custom_Duty: 15%; Customs_HS_Code: 85332119; Distributor_name: DIGIKEY; Distributor_part_number: 311-4186-1-ND; Footprint Path: Y:\MIS_DATABASE\Library\ALTIUM_TOOL\PCB_FOOTPRINTS\Altium_Footprint_Lib.PcbLib; Height: 1.45MM; Library Path: Y:\MIS_DATABASE\Library\ALTIUM_TOOL\SCHEMATICS_PARTS\MS_DISCRETE_Library.schlib; Manufacturer: YAGEO AMERICA; Mfr_name: YAGEO AMERICA; Mfr_part_number: CC0805GKNPO9BN272; Mistral Part No: 120020090023-R; Package: 0805; Part_type: CAPACITORS\CERAMIC; Project: TI_J7ES_CP; RoHS: RoHS; Temperature: -55°C+125°C; Tolerance: 2%; Voltage: 50V; Wattage: NA; Weight: 5.5mg; Datasheet: Y:\MIS_DATABASE\DATASHEETS\CAPACITORS\YACC-NPO.PDF
C239 = CAP: CAP CERAMIC 27pF 50V 1% C0G(NP0) 0805; Chkd/date: MANIRAJA/280920; Crtd /date: ALVY/250920; Custom_Duty: 15%; Customs_HS_Code: 85332119; Distributor_name: DIGIKEY; Distributor_part_number: 311-4173-1-ND; Footprint Path: Y:\MIS_DATABASE\Library\ALTIUM_TOOL\PCB_FOOTPRINTS\Altium_Footprint_Lib.PcbLib; Height: 0.70MM; Library Path: Y:\MIS_DATABASE\Library\ALTIUM_TOOL\SCHEMATICS_PARTS\MS_DISCRETE_Library.schlib; Manufacturer: YAGEO AMERICA; Mfr_name: YAGEO AMERICA; Mfr_part_number: CC0805FRNPO9BN270; Mistral Part No: 120020090022-R; Package: 0805; Part_type: CAPACITORS\CERAMIC; Project: TI_J7ES_CP; RoHS: RoHS; Temperature: -55°C+125°C; Tolerance: 1%; Voltage: 50V; Wattage: NA; Weight: 5.5mg; Datasheet: Y:\MIS_DATABASE\DATASHEETS\CAPACITORS\YACC-NPO.PDF
C248 = CAP_POL: CAP POLYMER 180uF 16V 20% C6CASE_6666; Chkd/date: MANIRAJA/171018; Crtd /date: ALVY/171018; Custom_Duty: 15%; Customs_HS_Code: 85322990; Direct Alternate_mfr_name: UNITED CHEMI-CON; Direct Alternate_mfr_part_number: APXG160ARA181MF61G; Distributor_name: DIGIKEY; Distributor_part_number: P16479CT-ND; Footprint Path: Y:\MIS_DATABASE\Library\ALTIUM_TOOL\PCB_FOOTPRINTS\Altium_Footprint_Lib.PcbLib; Height: 6.00MM; Library Path: Y:\MIS_DATABASE\Library\ALTIUM_TOOL\SCHEMATICS_PARTS\MS_DISCRETE_Library.schlib; Manufacturer: PANASONIC-ECG; Mfr_name: PANASONIC-ECG; Mfr_part_number: 16SVPF180M; Mistral Part No: 120018100030-R; Package: C6CASE_6666; Part_type: CAPACITORS\POLYPROPYLENE; Project: TI_J7ES_EVM_CP; RoHS: RoHS; Temperature: -55°C+105°C; Tolerance: 20%; Voltage: 16V; Wattage: NA; Weight: 270mg; Datasheet: Y:\MIS_DATABASE\DATASHEETS\CAPACITORS\SVPF-SER.PDF
D34 D35 = DIODE_SCHOTTKY: DIODE SCHOTTKY RECTIFIER 60V 1A SOD-123FL; Chkd/date: ALVY/240322; Crtd /date: TAMILARASU/220322; Custom_Duty: 15%; Customs_HS_Code: 85412900; Distributor_name: DIGIKEY; Distributor_part_number: RBR1MM60ACT-ND; Footprint Path: Y:\MIS_DATABASE\Library\ALTIUM_TOOL\PCB_FOOTPRINTS\Altium_Footprint_Lib.PcbLib; Height: 0.90MM; Library Path: Y:\MIS_DATABASE\Library\ALTIUM_TOOL\SCHEMATICS_PARTS\MS_DISCRETE_Library.schlib; Manufacturer: ROHM; Mfr_name: ROHM; Mfr_part_number: RBR1MM60ATR; Mistral Part No: 130022030051-R; Package: SOD-123FL; Part_type: DIODE\SCHOTTKY; Project: TI_J7AHP_EVM_BRD; RoHS: RoHS; Temperature: NA; Tolerance: NA; Voltage: 60V; Wattage: NA; Weight: 27.827mg; Datasheet: Y:\MIS_DATABASE\DATASHEETS\DISCRETES\DIODES\RBR1MM60A.PDF
L23 = INDUCTOR: IND POWER 1uH 24A 20% SMD; Chkd/date: ALVY/110320; Crtd /date: ALVY/110320; Custom_Duty: 24%; Customs_HS_Code: 85437099; Distributor_name: DIGIKEY; Distributor_part_number: 541-1017-1-ND; Footprint Path: Y:\MIS_DATABASE\Library\ALTIUM_TOOL\PCB_FOOTPRINTS\Altium_Footprint_Lib.PcbLib; Height: 3.50MM; Library Path: Y:\MIS_DATABASE\Library\ALTIUM_TOOL\SCHEMATICS_PARTS\MS_DISCRETE_Library.schlib; Manufacturer: VISHAY; Mfr_name: VISHAY; Mfr_part_number: IHLP5050CEER1R0M01; Mistral Part No: 130020030017-R; Package: SMD; Project: TI_J7ES_CP; RoHS: RoHS; Temperature: -55°C+125°C; Tolerance: 20%; Voltage: NA; Wattage: NA; Weight: NA; Datasheet: Y:\MIS_DATABASE\DATASHEETS\DISCRETES\INDUCTORS\IHLP5050CE-01-SER.PDF
L29 = INDUCTOR: IND POWER 4.7uH 11A 20% SMD; Chkd/date: VASANTHA/090317; Crtd /date: MANIRAJA/090317; Custom_Duty: 15%; Customs_HS_Code: 85412900; Distributor_name: MOUSER; Distributor_part_number: 994-XAL6060-472MEB; Footprint Path: Y:\MIS_DATABASE\Library\ALTIUM_TOOL\PCB_FOOTPRINTS\Altium_Footprint_Lib.PcbLib; Height: 6.10MM; Library Path: Y:\MIS_DATABASE\Library\ALTIUM_TOOL\SCHEMATICS_PARTS\MS_DISCRETE_Library.schlib; Manufacturer: COILCRAFT; Mfr_name: COILCRAFT; Mfr_part_number: XAL6060-472MEB; Mistral Part No: 130015090013-R; Package: SMD; Project: OCTBTS_3000; RoHS: RoHS; Temperature: -40°C+125°C; Tolerance: 20%; Voltage: NA; Wattage: NA; Weight: 1600g; Datasheet: Y:\MIS_DATABASE\DATASHEETS\DISCRETES\INDUCTORS\XAL6060-SER.PDF
LD7 = LED_598-8170-107F: LED ALINGAP GREEN CLEAR 0805; Chkd/date: MANIRAJA/230817; Crtd /date: SARANYA/070514; Custom_Duty: 24%; Customs_HS_Code: 85437099; Distributor_name: DIGIKEY; Distributor_part_number: 350-2044-1-ND; Footprint Path: Y:\MIS_DATABASE\Library\ALTIUM_TOOL\PCB_FOOTPRINTS\Altium_Footprint_Lib.PcbLib; Height: 0.70MM; Manufacturer: DIALIGHT; Mfr_name: DIALIGHT; Mistral Part No: 130014050065-R; Package: 0805; Part_type: OPTO\LED; Project: AEGIS GP BETA2; RoHS: RoHS; Temperature: -30°C+85°C; Tolerance: NA; Voltage: NA; Wattage: NA; Weight: NA; Datasheet: Y:\MIS_DATABASE\DATASHEETS\DISCRETES\LEDS\598-SER.PDF
R181 R308 = RESISTOR_KRL_TI: RES 0.005E 1.5W 1% 1206-W; Chkd/date: MANIRAJA/020819; Crtd /date: ALVY/010819; Custom_Duty: 15%; Customs_HS_Code: 85332119; Distributor_name: MOUSER; Distributor_part_number: 754-KRL3216ECR005FT1; Footprint Path: Y:\MIS_DATABASE\Library\ALTIUM_TOOL\PCB_FOOTPRINTS\Altium_Footprint_Lib.PcbLib; Height: 0.70MM; Library Path: Y:\MIS_DATABASE\Library\ALTIUM_TOOL\SCHEMATICS_PARTS\MS_DISCRETE_Library.schlib; Mfr_name: SUSUMU; Mfr_part_number: KRL3216E-C-R005-F-T1_TI; Mistral Part No: 110019080004-R; Package: 1206-W; Part_type: RESISTORS\FIXED; Project: J7ES_SOM_DUAL-LEO_PMIC; RoHS: RoHS; Temperature: -55°C+175°C; Tolerance: 1%; Voltage: NA; Wattage: 1.5W; Weight: NA; Datasheet: Y:\MIS_DATABASE\DATASHEETS\RESISTORS\KRL_TI-SERIES.PDF
R184 = RESISTOR: RES 100E 1/10W 1% 0402; Chkd/date: MANIRAJA/130617; Crtd /date: JEBRAN/040715; Custom_Duty: 15%; Customs_HS_Code: 85332119; Distributor_name: DIGIKEY; Distributor_part_number: P100LCT-ND; Footprint Path: Y:\MIS_DATABASE\Library\ALTIUM_TOOL\PCB_FOOTPRINTS\Altium_Footprint_Lib.PcbLib; Height: 0.40MM; Library Path: Y:\MIS_DATABASE\Library\ALTIUM_TOOL\SCHEMATICS_PARTS\MS_DISCRETE_Library.schlib; Manufacturer: PANASONIC-ECG; Mfr_name: PANASONIC-ECG; Mfr_part_number: ERJ-2RKF1000X; Mistral Part No: 110018020036-R; Package: 0402; Part_type: RESISTORS\FIXED; Project: CYPHY_FVB; RoHS: RoHS; Temperature: -55°C+155°C; Tolerance: 1%; Voltage: NA; Wattage: 1/10W; Weight: 0.8mg; Datasheet: Y:\MIS_DATABASE\DATASHEETS\RESISTORS\PAN-ERJSER_NOV17.PDF
R187 = RESISTOR: RES CURRENT SENSE 0.003E 1.5W 2% 0612; Chkd/date: ALVY/110320; Crtd /date: ALVY/110320; Custom_Duty: 15%; Customs_HS_Code: 85332119; Distributor_name: DIGIKEY; Distributor_part_number: FCSL32R003GERCT-ND; Footprint Path: Y:\MIS_DATABASE\Library\ALTIUM_TOOL\PCB_FOOTPRINTS\Altium_Footprint_Lib.PcbLib; Height: 0.60MM; Library Path: Y:\MIS_DATABASE\Library\ALTIUM_TOOL\SCHEMATICS_PARTS\MS_DISCRETE_Library.schlib; Manufacturer: OHMITE; Mfr_name: OHMITE; Mfr_part_number: FCSL32R003GER; Mistral Part No: 110020030026-R; Package: 0612; Part_type: RESISTORS\FIXED; Project: TI_J7ES_CP; RoHS: RoHS; Temperature: -55°C+155°C; Tolerance: 2%; Voltage: NA; Wattage: 1.5W; Weight: 30mg; Datasheet: Y:\MIS_DATABASE\DATASHEETS\RESISTORS\FCSL-SER.PDF
R252 R254 R272 R277 R940 R950 = RESISTOR: RES 10.5E 1/16W 1% 0402; Chkd/date: MANIRAJA/110918; Crtd /date: ALVY/110918; Custom_Duty: 15%; Customs_HS_Code: 85332119; Distributor_name: DIGIKEY; Distributor_part_number: 541-10.5LCT-ND; Footprint Path: Y:\MIS_DATABASE\Library\ALTIUM_TOOL\PCB_FOOTPRINTS\Altium_Footprint_Lib.PcbLib; Height: 0.40MM; Library Path: Y:\MIS_DATABASE\Library\ALTIUM_TOOL\SCHEMATICS_PARTS\MS_DISCRETE_Library.schlib; Manufacturer: VISHAY; Mfr_name: VISHAY; Mfr_part_number: CRCW040210R5FKED; Mistral Part No: 110018090012-R; Package: 0402; Part_type: RESISTORS\FIXED; Project: TI_J7ES_EVM_CP; RoHS: RoHS; Temperature: -55°C+155°C; Tolerance: 1%; Voltage: NA; Wattage: 1/16W; Weight: 0.65mg; Datasheet: Y:\MIS_DATABASE\DATASHEETS\RESISTORS\CRCW0603.PDF
R279 = RESISTOR: RES 11.8K 1/16W 1% 0402; Chkd/date: MANIRAJA/280920; Crtd /date: ALVY/250920; Custom_Duty: 15%; Customs_HS_Code: 85332119; Distributor_name: DIGIKEY; Distributor_part_number: YAG2958CT-ND; Footprint Path: Y:\MIS_DATABASE\Library\ALTIUM_TOOL\PCB_FOOTPRINTS\Altium_Footprint_Lib.PcbLib; Height: 0.40MM; Library Path: Y:\MIS_DATABASE\Library\ALTIUM_TOOL\SCHEMATICS_PARTS\MS_DISCRETE_Library.schlib; Manufacturer: YAGEO AMERICA; Mfr_name: YAGEO AMERICA; Mfr_part_number: RC0402FR-0711K8L; Mistral Part No: 110015080036-R; Package: 0402; Part_type: RESISTORS\FIXED; Project: TI_J7ES_CP; RoHS: RoHS; Temperature: -55°C+155°C; Tolerance: 1%; Voltage: NA; Wattage: 1/16W; Weight: 12mg; Datasheet: Y:\MIS_DATABASE\DATASHEETS\RESISTORS\RCXXXXL-SER_MAR18.PDF
TP75 TP147 = TESTPOINT: TESTPOINT CIR 40 SMD; Chkd/date: MAZHAR/190505; Crtd /date: MAZHAR/190505; Distributor_name: NA; Distributor_part_number: NA; Footprint Path: Y:\MIS_DATABASE\Library\ALTIUM_TOOL\PCB_FOOTPRINTS\Altium_Footprint_Lib.PcbLib; Height: NA; Library Path: Y:\MIS_DATABASE\Library\ALTIUM_TOOL\SCHEMATICS_PARTS\MS_DISCRETE_Library.schlib; MECHANICAL 3D STEP FILE: NA; Manufacturer: LOCAL; Mfr_name: LOCAL; Mistral Part No: 130009030933; Package: SMD; Project: RAINIER-3; RoHS: NA; Temperature: NA; Tolerance: NA; Voltage: NA; Wattage: NA; Weight: NA; Datasheet: NA
U46 = LM5140QRWGTQ1_VQFNP40_TI: IC WIDE I/P DUAL SYNCHRONOUS BUCK CONTROLLER VQFNP40; Chkd/date: MANIRAJA/041017; Crtd /date: MANIRAJA/041017; Custom_Duty: 15%; Customs_HS_Code: 85423100; Distributor_name: DIGIKEY; Distributor_part_number: 296-43790-1-ND; Footprint Path: Y:\MIS_DATABASE\Library\ALTIUM_TOOL\PCB_FOOTPRINTS\Altium_Footprint_Lib.PcbLib; Height: 0.90MM; Library Path: Y:\MIS_DATABASE\Library\ALTIUM_TOOL\SCHEMATICS_PARTS\MS_MISCPOWER_Library.schlib; Library Ref: LM5140QRWGTQ1_VQFNP40; Manufacturer: TEXAS INSTRUMENTS; Mfr_name: TEXAS INSTRUMENTS; Mistral Part No: 142017100003-R; Package: VQFNP40; Part_type: ICS\POWER\CONVERTER; Project: TI_MAXIE_CPB; RoHS: RoHS; Temperature: -40°C+150°C; Tolerance: NA; Voltage: NA; Wattage: NA; Weight: 104mg; Datasheet: Y:\MIS_DATABASE\DATASHEETS\ICS\POWER\LM5140QRWGXX.PDF

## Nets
DGND: C150.1 C172.2 C173.2 C174.2 C194.2 C195.2 C199.2 C205.2 C217.2 C219.1 C221.1 C222.1 C223.2 C235.2 C238.2 C239.2 C248.2 C252.1 C280.2 C287.2 C290.2 C295.1 C301.2 C305.2 C306.2 C308.2 C314.2 C318.2 C321.1 C1038.2 C1055.2 LD7.1 R466.2 R492.2 U44.1(S1) U44.2(S2) U44.3(S3) U46.14(PGND2) U46.17(PGND1) U46.35(AGND) U46.37(OSC) U46.38(SYNIN) U46.41(EP) U51.1(S1) U51.2(S2) U51.3(S3) U81.3(AGND) U81.6(OSC) U81.9(PGND) U81.16(VCCX) U81.25(EP) U81.A1 U81.A2 U81.A3 U81.A4 U240.1(S1) U240.2(S2) U240.3(S3) ; also on sheet 11 12 13 14 15 16 17 18 20 21 22 23 24 25 26 27 28 29 30 31 32 33 34 35 36 37 38 39 40 41 42 43 44 45 46 47 48 49 50 51 52 53 54 55 56 57 58 59 60 61 62 63 64 67 68 69 70 71 72 73 76 77 78 79 81 82 83 84
V5V0: C248.1 C252.2 R289.2 R308.1 R308.2 R308.3 R357.2 U46.6(VCCX)
VCC_12V0: R418.2 R465.1 TP133.1(TP) ; also on sheet 30 31 46 50 53 59 60 64 83
VCC_12V0_N: R418.1 ; also on sheet 77
VCC_12V0_P: R418.4 ; also on sheet 77
VCC_LM5140: C219.2 C222.2 D34.2(ANODE) D35.2(ANODE) U46.15(VCC) U46.16(VCC)
VCC_LM5141: C308.1 D38.2(ANODE) U81.10(VCC)
VDDA_LM5140: C221.2 U46.3(FB2) U46.28(FB1) U46.33(DEMB) U46.34(ILSET) U46.36(VDDA)
VDDA_LM5141: C321.2 U81.1(DEMB) U81.2(VDDA) U81.5(DITH)
VINPUT: C199.1 C235.1 C280.1 C301.1 C1038.1 C1055.1 U45.5(D) U46.25(VIN) U49.5(D) U81.15(VIN) U237.5(D) ; also on sheet 36 64 67
COMP1_LM5140: C195.1 R253.2 U46.29(COMP1)
COMP2_LM5140: C239.1 R279.1 U46.2(COMP2)
COMP_LM5141: C306.1 R473.1 U81.20(COMP)
CS1_LM5140: C202.2 R244.2 U46.27(CS1)
CS2_LM5140: C234.1 R288.2 U46.4(CS2)
CS_LM5141: L35.2 R449.1 U81.18(CS)
EN1_LM5140: R255.1 U46.31(EN1)
EN2_LM5140: R271.1 R1308.1 U46.40(EN2)
EN_3V3_VIO: R1308.2 ; also on sheet 54 69 72
EN_LM5141_ON: R481.1 R1305.1 U81.23(EN)
EXP_3V3: R181.4 R181.6 ; also on sheet 30 31 59 60
EXP_3V3_N: R181.5 TP32.1(TP)
EXP_3V3_P: R181.2 TP36.1(TP)
FB_LM5141: R465.2 R466.1 U81.19(FB)
HB1: C201.2 D34.1(CATHODE) U46.20(HB1)
HB2: C232.1 D35.1(CATHODE) U46.11(HB2)
HB_LM5141: C302.2 D38.1(CATHODE) U81.11(HB)
HO1: R252.2 U46.22(HO1)
HO2: R277.1 U46.9(HO2)
HO_LM5141: R464.1 U81.13(HO)
HOL1: R252.1 U45.4(G) U46.23(HOL1)
HOL2: R277.2 U46.8(HOL2) U49.4(G)
HOL_LM5141: R464.2 U81.14(HOL) U237.4(G)
LM5140_LO1: R254.1 R940.1 U44.4(G)
LM5140_LO2: R272.2 R950.2 U51.4(G)
LM5140_PG1: R939.1 U46.24(PG1) ; also on sheet 36
LM5140_PG2: R956.1 U46.7(PG2) ; also on sheet 36
LM5140_SW1: C201.1 L23.2 U44.5(D) U45.1(S1) U45.2(S2) U45.3(S3) U46.21(SW1)
LM5140_SW2: C232.2 L29.1 U46.10(SW2) U49.1(S1) U49.2(S2) U49.3(S3) U51.5(D)
LM5141_PG: R1131.1 U81.21(PG) ; also on sheet 36
LO1: R254.2 U46.18(LO1)
LO2: R272.1 U46.13(LO2)
LO_LM5141: R482.1 U81.8(LO)
LOL1: R940.2 U46.19(LOL1)
LOL2: R950.1 U46.12(LOL2)
LOL_LM5141: R488.1 U81.7(LOL)
RES_LM5140: C217.1 U46.32(RES)
RES_LM5141: C318.1 U81.24(RES)
RT_LM5141: R492.1 U81.4(RT)
SS1_LM5140: C205.1 U46.30(SS1)
SS2_LM5140: C223.1 U46.1(SS2)
SS_LM5141: C314.1 U81.22(SS)
SW_LM5141: C302.1 L35.1 U81.12(SW) U237.1(S1) U237.2(S2) U237.3(S3) U240.5(D)
SYNOUT_LM5140: TP75.1(TP) U46.39(SYNOUT)
V_12V0: C287.1 C290.1 C295.2 R418.3 R449.2 U81.17(VOUT)
VEXP_3V3: C150.2 C172.1 C173.1 C174.1 R181.1 R181.3 R187.1 R245.2
VSYS_3V3: R184.1 R481.2 R939.2 R956.2 R1131.2 TP27.1(TP) ; also on sheet 22 23 35 36 40 47 49 62 63 67 68 69 73 75 76 77 78 79
VSYS_5V0: R357.3 TP108.1(TP) ; also on sheet 20 30 31 50 52 59 68 72 81 82 83 84
VSYS_5V0_N: R357.4 ; also on sheet 77
VSYS_5V0_P: R357.1 ; also on sheet 77
VSYS_IO_1V8: TP10.1(TP) ; also on sheet 30 32 33 34 37 38 41 42 61 75
VSYS_IO_3V3: R255.2 R271.2 R1305.2 TP227.1(TP) ; also on sheet 18 20 22 24 29 30 31 32 33 35 36 37 38 40 41 42 43 45 46 48 50 51 53 56 57 58 59 60 61 68 75 81 82
VSYS_MCUIO_1V8: TP147.1(TP) ; also on sheet 17 21 37 39 53 62 75
VSYS_MCUIO_3V3: TP213.1(TP) ; also on sheet 16 17 18 21 22 23 35 36 43 44 48 49 55 62 68 75
N24011787: L29.2 R288.1 R308.4 R308.5 R308.6
N24011809: C234.2 R289.1 U46.5(VOUT2)
N24011946: L23.1 R187.2 R244.1
N24012043: C202.1 R245.1 U46.26(VOUT1)
N24132464: C238.1 R279.2
N24135121: C194.1 R253.1
N27374629: LD7.2 R184.2
N34514277: C305.1 R473.2
N34514391: R482.2 R488.2 U240.4(G)

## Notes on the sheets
sheet 65
- POWER SUPPLY #3
- 3.3V AND 5V GENERATION
- FB1 connected to VDDA to set VOUT1=3.3V
  FB2 connected to VDDA to set VOUT2=5V
- PCB Note: Short LM5140_AGND and DGND at single point
- OSC pin to VCC sets fs=2.2MHz
  OSC pin to GND sets fs=440kHz
- DEMB-VDDA- FPWM mode operation
  DEMB-GND- enables diode emulation
- ILSET pin to VDDA sets current limit
  threshold to 73 mV
  ILSET pin to GND sets current limit
  threshold to 48 mV
- Silkscreen:"VSYS_3V3"
sheet 66
- POWER SUPPLY #2
- PCB Note: Short LM5141_AGND and DGND at single point
